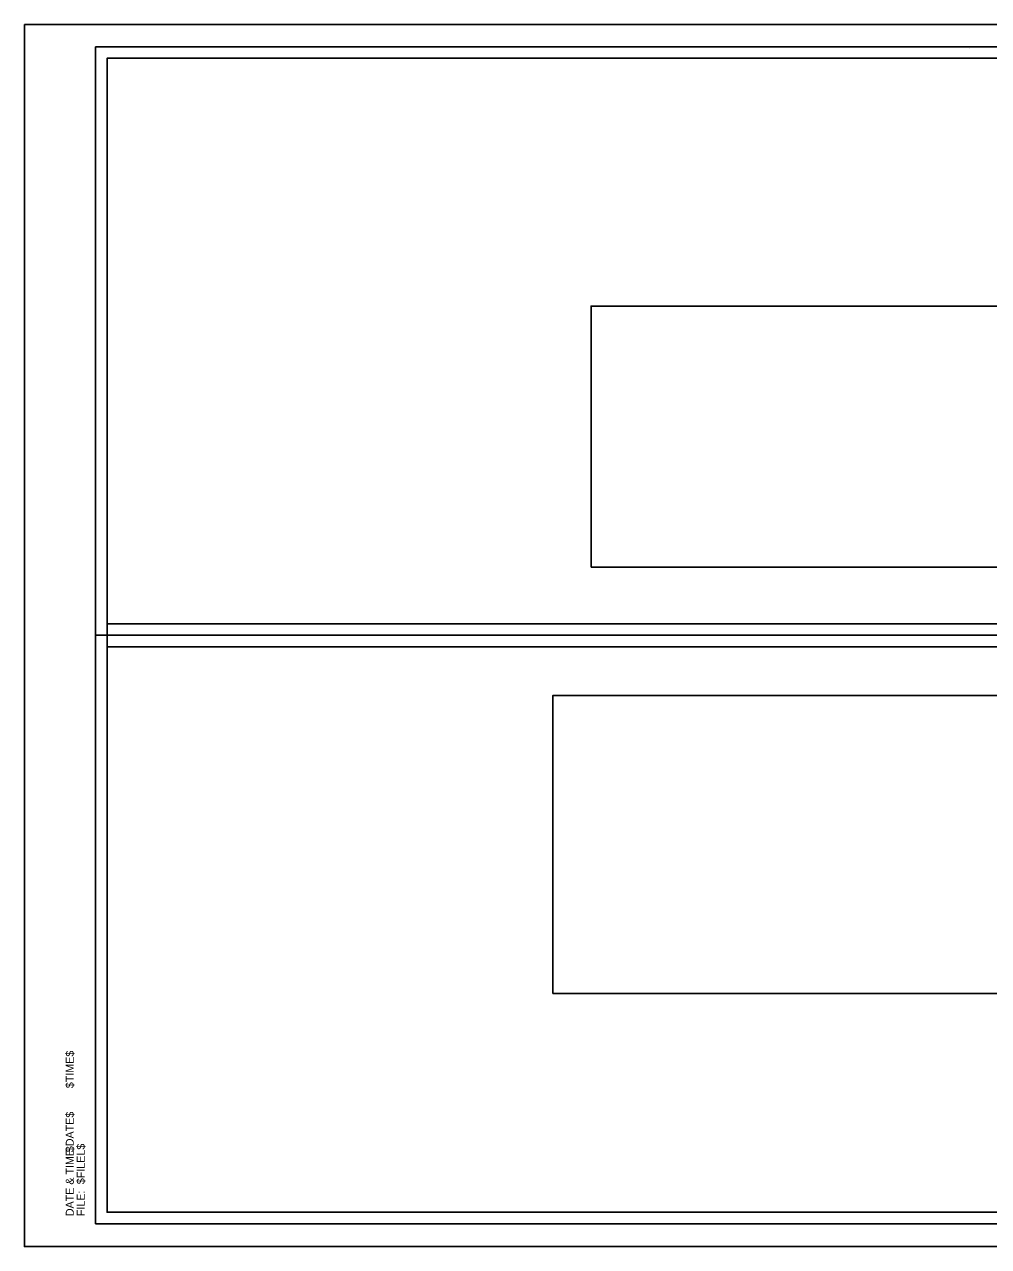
# Model space of a CAD drawing. Extents: x 1369905 to 1370238, y 380119 to 380332.
# Drawn here: x 1369904.6 to 1370072.9, y 380119.1 to 380332.4 of the extents above; entities that cross this region are included whole.
import ezdxf

# ---------------------------------------------------------------- set-up
doc = ezdxf.new("R2010")
doc.units = 0
for name, color, linetype in [('Default', 7, 'Continuous'), ('R_Border', 7, 'Continuous'), ('R_Border Notes', 7, 'Continuous'), ('R_Border Plan-Plan', 7, 'Continuous'), ('R_No Plot', 7, 'Continuous')]:
    doc.layers.add(name, color=color, linetype=linetype)

msp = doc.modelspace()

# ---------------------------------------------------------------- linework, layer by layer
at = {"layer": 'Default'}
for points in [[(1370003.51, 380237.69), (1370148.12, 380237.69), (1370148.12, 380283.26), (1370003.51, 380283.26)], [(1369996.82, 380163.24), (1370154.81, 380163.24), (1370154.81, 380215.25), (1369996.82, 380215.25)]]:
    msp.add_lwpolyline(points, close=True, dxfattribs=at)
at = {"layer": 'R_Border'}
for p, q in [((1369917.04, 380328.52), (1370233.22, 380328.52)), ((1369917.04, 380123.06), (1369917.04, 380328.52)), ((1370069.56, 380328.26), (1370069.56, 380328.26)), ((1370069.56, 380328.26), (1370069.56, 380328.26)), ((1369917.04, 380123.06), (1369917.04, 380123.06)), ((1370233.22, 380123.06), (1369917.04, 380123.06))]:
    msp.add_line(p, q, dxfattribs=at)
at = {"layer": 'R_Border Plan-Plan'}
msp.add_line((1369917.04, 380225.79), (1370233.22, 380225.79), dxfattribs=at)
at = {"layer": 'R_No Plot'}
for points in [[(1369904.63, 380332.42), (1370237.97, 380332.42), (1370237.97, 380119.08), (1369904.63, 380119.08)], [(1370231.22, 380227.79), (1369919.04, 380227.79), (1369919.04, 380326.52), (1370168.58, 380326.52), (1370168.58, 380316.64), (1370186.12, 380316.64), (1370210.22, 380316.64), (1370210.22, 380294.31), (1370231.22, 380294.31)], [(1369919.04, 380326.52), (1370168.58, 380326.52), (1370168.58, 380316.64), (1370186.12, 380316.64), (1370210.22, 380316.64), (1370210.22, 380294.31), (1370231.22, 380294.31), (1370231.22, 380125.06), (1369919.04, 380125.06)], [(1369919.04, 380223.79), (1370231.22, 380223.79), (1370231.22, 380125.06), (1369919.04, 380125.06)]]:
    msp.add_lwpolyline(points, close=True, dxfattribs=at)

# ---------------------------------------------------------------- texts
at = {"layer": 'R_Border Notes'}
for s, height, p in [('$TIME$', 1.397, (1369913.24, 380146.73)), ('$DATE$', 1.397, (1369913.24, 380135.56)), ('DATE & TIME:', 1.3968, (1369913.24, 380124.39)), ('$FILEL$', 1.397, (1369915.16, 380129.97)), ('FILE: ', 1.397, (1369915.16, 380124.39))]:
    msp.add_text(s, height=height, rotation=90, dxfattribs=at).set_placement(p)

doc.saveas('drawing.dxf')
